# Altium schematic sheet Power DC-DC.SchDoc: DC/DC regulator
size 431 x 279 mm; Date: Not shown in title block; ApprovedBy: Not shown in title block; CheckedBy: Not shown in title block; Author: Not shown in title block; CompanyName: Not shown in title block; Engineer: Not shown in title block; Organization: Not shown in title block; Address1: Not shown in title block; Address2: Not shown in title block; Address3: Not shown in title block; Address4: Not shown in title block; DocumentNumber: 1; Revision: Use project parameter SCH_Rev; SheetNumber: 3; SheetTotal: 15; PageSetup: Record=PageOptions¦CenterHorizontal=True¦CenterVertical=True¦PrintScale=1.00¦XCorrection=1.00¦YCorrection=1.00¦PrintKind=0¦BorderSize=5000000¦LeftOffset=0¦BottomOffset=0¦Orientation=2¦PaperLength=1000¦PaperWidth=1000¦Scale=100¦PaperSource=15¦PrintQuality=600¦MediaType=1¦DitherType=10¦PaperKind=Letter¦PrintScaleMode=1
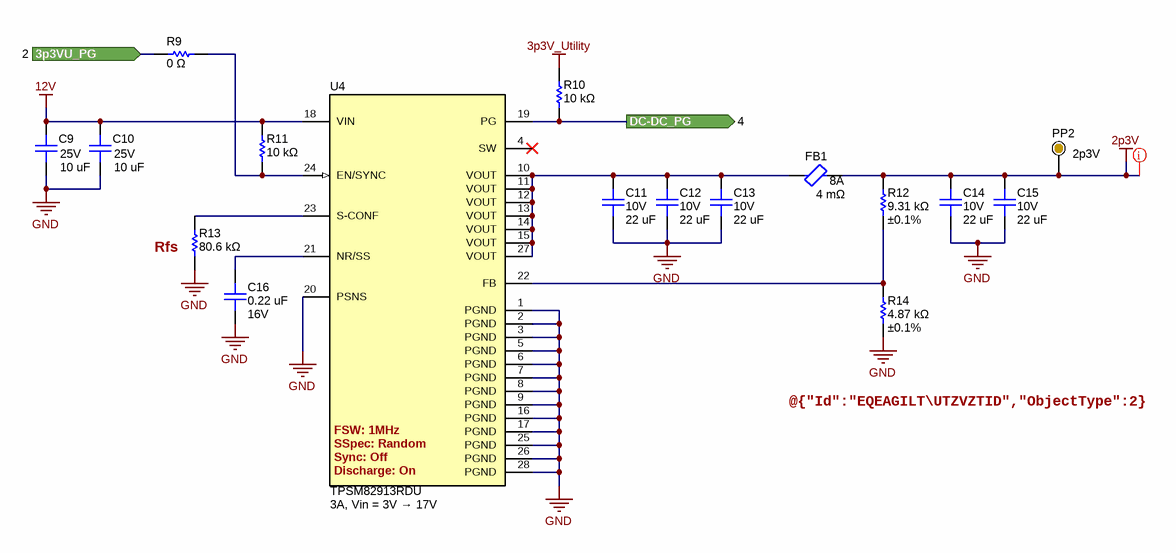
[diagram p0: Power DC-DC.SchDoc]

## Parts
C9  value 10 uF  Voltage - Rated: 25V  [0805L_cap]  (hidden comment: C2012X7S1E106K125AC)
C10  value 10 uF  Voltage - Rated: 25V  [0805L_cap]  (hidden comment: C2012X7S1E106K125AC)
C11  value 22 uF  Voltage - Rated: 10V  [0805L_cap]  (hidden comment: C2012X7S1A226M125AC)
C12  value 22 uF  Voltage - Rated: 10V  [0805L_cap]  (hidden comment: C2012X7S1A226M125AC)
C13  value 22 uF  Voltage - Rated: 10V  [0805L_cap]  (hidden comment: C2012X7S1A226M125AC)
C14  value 22 uF  Voltage - Rated: 10V  [0805L_cap]  (hidden comment: C2012X7S1A226M125AC)
C15  value 22 uF  Voltage - Rated: 10V  [0805L_cap]  (hidden comment: C2012X7S1A226M125AC)
C16  value 0.22 uF  Voltage - Rated: 16V  [0402L_cap]  (hidden comment: CGA2B1X5R1C224M050BC)
FB1  DCR: 4 mΩ  Current: 8A  [0603L]  (hidden comment: BLE18PS080SN1D)
PP2  Text1: 2p3V  [ProbePoint_TH_40mil]  (hidden comment: Probe Point)  (no BOM)
R9  value 0 Ω  [0402L]  (hidden comment: ERJ-U020R00X)
R10  value 10 kΩ  [0402L]  (hidden comment: ERA-2AEB103X)
R11  value 10 kΩ  [0402L]  (hidden comment: ERJ-2RKF1002X)
R12  value 9.31 kΩ  Tolerance: ±0.1%  [0402L]  (hidden comment: ERA-2AEB9311X)
R13  value 80.6 kΩ  [0402L]  (hidden comment: ERJ-2RKF8062X)
R14  value 4.87 kΩ  Tolerance: ±0.1%  [0402L]  (hidden comment: ERA-2AEB4871X)
U4  TPSM82913RDU  Text1: 3A, Vin = 3V → 17V  Discharge: On  Sync: Off  SSpec: Random  FSW: 1MHz  [RDU0028A]

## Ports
3p3VU_PG (in, see 2), DC-DC_PG (out, see 4)

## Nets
2p3V: C14.2 C15.2 FB1.2 PP2.1 R12.2
3p3V_Utility: R10.2
12V: C9.2 C10.2 R11.2 U4.18(VIN)
GND: C9.1 C10.1 C11.1 C12.1 C13.1 C14.1 C15.1 C16.2 R13.1 R14.1 U4.1(PGND) U4.2(PGND) U4.3(PGND) U4.5(PGND) U4.6(PGND) U4.7(PGND) U4.8(PGND) U4.9(PGND) U4.16(PGND) U4.17(PGND) U4.20(PSNS) U4.25(PGND) U4.26(PGND) U4.28(PGND)
3p3VU_PG: R9.2 ; port 3p3VU_PG
DC-DC_PG: R10.1 U4.19(PG) ; port DC-DC_PG
NetC11_2: C11.2 C12.2 C13.2 FB1.1 U4.10(VOUT) U4.11(VOUT) U4.12(VOUT) U4.13(VOUT) U4.14(VOUT) U4.15(VOUT) U4.27(VOUT)
NetC16_1: C16.1 U4.21(NR/SS)
NetR9_1: R9.1 R11.1 U4.24(EN/SYNC)
NetR12_1: R12.1 R14.2 U4.22(FB)
NetR13_2: R13.2 U4.23(S-CONF)

Not connected (* = marked no-connect by the designer): U4 4(SW)*

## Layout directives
net class Power; net class GenPwr: 2p3V

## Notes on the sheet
- (near R13) Rfs
- @{"Id":"EQEAGILT\UTZVZTID","ObjectType":2} = @{"Id":"EQEAGILT\NLLUWDBR","ObjectType":2} *(VOUT/0.8 -1)

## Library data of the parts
C9 C10 = capcc03511: CAP CER 10UF 25V X7S 0805; Manufacturer: TDK Corporation; CompType: Capacitor Ceramic; Tolerance: ±10%; SizeX_mm: 2; SizeY_mm: 1.25; SizeZ_mm: 1.5
C11-C15 = capcc09395: CAP CER 22UF 10V X7S 0805; Manufacturer: TDK Corporation; CompType: Capacitor Ceramic; Tolerance: ±20%; SizeX_mm: 2; SizeY_mm: 1.25; SizeZ_mm: 1.45
C16 = capcc01693: CAP CER 0.22UF 16V X5R 0402; Manufacturer: TDK Corporation; CompType: Capacitor Ceramic; Tolerance: ±20%; SizeX_mm: 1; SizeY_mm: 0.5; SizeZ_mm: 0.55
FB1 = dcp00004: 8.5 Ohms @ 100 MHz 1 Power Line Ferrite Bead 0603 (1608 Metric) 8A 4mOhm; Manufacturer: Murata; Impedance: 8.5 Ω; SizeX_mm: 1.6; SizeY_mm: 0.8
PP2 = cmp00025: Probe Point that can be used in lue of a test point
R9 = RSMD040200004: RES 0 OHM JUMPER 0402 SMD; Manufacturer: Panasonic Electronic Components; CompType: Resistor SMD; Power (Watts): 0.1W, 1/10W; Temperature Coefficient: -100/ +600ppm/°C; SizeX_mm: 1; SizeY_mm: 0.5; SizeZ_mm: 0.4
R10 = RSMD040200315: RES SMD 10K OHM 0.1% 1/16W 0402; Manufacturer: Panasonic Electronic Components; CompType: Resistor SMD; Power (Watts): 0.063W, 1/16W; Temperature Coefficient: ±25ppm/°C; SizeX_mm: 1; SizeY_mm: 0.5; SizeZ_mm: 0.4
R11 = RSMD040200314: RES SMD 10K OHM 1% 1/10W 0402; Manufacturer: Panasonic Electronic Components; CompType: Resistor SMD; Power (Watts): 0.1W, 1/10W; Temperature Coefficient: ±100ppm/°C; SizeX_mm: 1; SizeY_mm: 0.5; SizeZ_mm: 0.4
R12 = RSMD040203923: RES SMD 9.31KOHM 0.1% 1/16W 0402; Manufacturer: Panasonic Electronic Components; CompType: Resistor SMD; Power (Watts): 0.063W, 1/16W; Temperature Coefficient: ±25ppm/°C; SizeX_mm: 1; SizeY_mm: 0.5; SizeZ_mm: 0.4
R13 = RSMD040203748: RES SMD 80.6K OHM 1% 1/10W 0402; Manufacturer: Panasonic Electronic Components; CompType: Resistor SMD; Power (Watts): 0.1W, 1/10W; Temperature Coefficient: ±100ppm/°C; SizeX_mm: 1; SizeY_mm: 0.5; SizeZ_mm: 0.4
R14 = RSMD040202615: RES SMD 4.87KOHM 0.1% 1/16W 0402; Manufacturer: Panasonic Electronic Components; CompType: Resistor SMD; Power (Watts): 0.063W, 1/16W; Temperature Coefficient: ±25ppm/°C; SizeX_mm: 1; SizeY_mm: 0.5; SizeZ_mm: 0.4
U4 = cmp00201: 3-V to 17-V, 3-A Low-Noise and Low-Ripple Buck Power Module with Integrated Ferrite Bead Filter Compensation; Part Number: TPSM82913RDUR; Manufacturer: Texas Instruments; Switching Frequency: 1/2.2MHz; Max Duty Cycle: 100%; Output Voltage: 0.8-5.5V; Standoff Height: 0mm; CompType: Switcher; Number Of Outputs: 1; Max Supply Voltage: 17V; AEC Category: Q200; TJmax_C: +125°C; Nominal Supply Current: 5mA; Output Type: AdjustableProgrammable; Min Supply Voltage: 3V; AEC Qualified: No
